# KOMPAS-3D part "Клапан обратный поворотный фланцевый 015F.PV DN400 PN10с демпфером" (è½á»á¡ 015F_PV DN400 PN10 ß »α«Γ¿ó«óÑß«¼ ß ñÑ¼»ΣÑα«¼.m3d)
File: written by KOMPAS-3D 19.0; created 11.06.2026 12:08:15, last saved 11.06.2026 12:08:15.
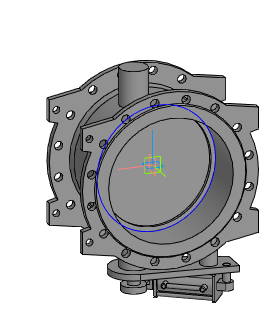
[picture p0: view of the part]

Document properties: Автор: Энергия; Полное имя файла: Z:\3.Личные\kachalov\001_3d для проектировщиков\5.5 Тип 015F.PV Клапан обратный поворотный с двумя эксцентриками\_stp_Клапан 015F.PV DN300-DN1200 с противовесом с демпфером\Клапан 015F_PV DN400 PN10 с противовесом с демпфером.m3d

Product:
- Part/product: Клапан обратный поворотный фланцевый 015F.PV DN400 PN10с демпфером

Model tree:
1. Операция без истории:1
2. Сплайн:1
     Координата Y = 30; Координата Z = 200; Вес = 1; Координата X = 400; Координата Y = 82.661; Координата Z = 200; Вес = 0.333333; Координата X = 400; Координата Y = 82.661; Координата Z = -200; Вес = 0.333333; Координата Y = 30; Координата Z = -200; Вес = 1; Координата X = -400; Координата Y = -22.661; Координата Z = -200; Вес = 0.333333; Координата X = -400; Координата Y = -22.661; Координата Z = 200; Вес = 0.333333; Порядок = 4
